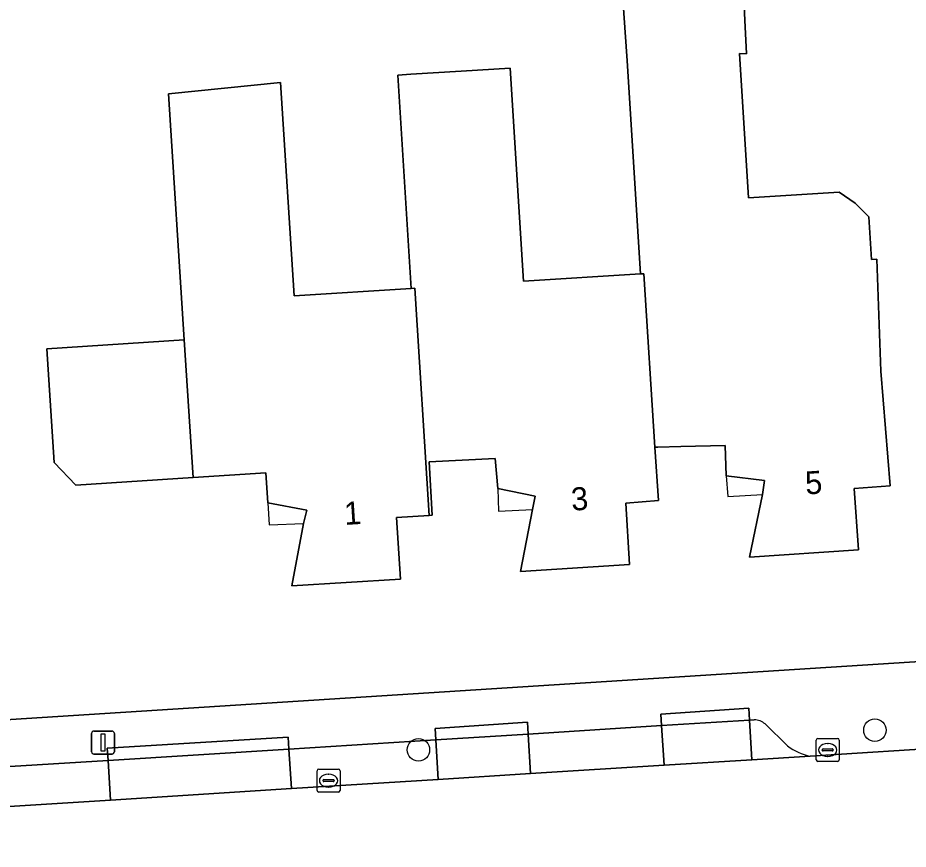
# Model space of a CAD drawing. Extents: x 159626 to 160723, y 388173 to 389416.
# Drawn here: x 160548.37 to 160587.15, y 388427.71 to 388463.92 of the extents above; entities that cross this region are included whole.
import ezdxf

# ---------------------------------------------------------------- set-up
doc = ezdxf.new("R2010")
doc.units = 0
for name, color, linetype in [('IMGEO_Boom', 7, 'Continuous'), ('IMGEO_Erf', 7, 'Continuous'), ('IMGEO_Kolk', 7, 'Continuous'), ('IMGEO_Lichtmast', 7, 'Continuous'), ('IMGEO_Pand', 7, 'Continuous'), ('IMGEO_Pand_nummerreeks', 7, 'Continuous'), ('IMGEO_Pand_overbouw', 7, 'Continuous'), ('IMGEO_Parkeervlak_open', 7, 'Continuous'), ('IMGEO_Rijbaan_lokaal_open', 7, 'Continuous'), ('IMGEO_Voetpad_open', 7, 'Continuous')]:
    doc.layers.add(name, color=color, linetype=linetype)

msp = doc.modelspace()

# ---------------------------------------------------------------- linework, layer by layer
at = {"layer": 'IMGEO_Boom'}
for centre in [(160585.699, 388432.889), (160565.815, 388432.036)]:
    msp.add_circle(centre, 0.489, dxfattribs=at)
at = {"layer": 'IMGEO_Erf'}
for points in [[(160579.903, 388466.467), (160580.102, 388462.353), (160579.794, 388462.358), (160580.19, 388456.07), (160584.142, 388456.319), (160584.842, 388455.845), (160585.435, 388455.244), (160585.551, 388453.398), (160585.781, 388453.412), (160585.963, 388448.525), (160586.361, 388443.54), (160584.797, 388443.415), (160584.985, 388440.742), (160580.238, 388440.423), (160580.798, 388443.162), (160580.883, 388443.764), (160579.227, 388443.972), (160579.173, 388445.293), (160577.242, 388445.247), (160576.242, 388445.223), (160576.12, 388445.22), (160576.268, 388442.893), (160574.857, 388442.774), (160575.008, 388440.107), (160570.266, 388439.795), (160570.787, 388442.508), (160570.899, 388443.089), (160569.275, 388443.41), (160569.151, 388444.72), (160566.289, 388444.583), (160566.417, 388442.257), (160566.286, 388442.248), (160564.857, 388442.148), (160565.035, 388439.474), (160560.297, 388439.172), (160560.808, 388441.896), (160560.958, 388442.477), (160559.253, 388442.798), (160559.165, 388444.104), (160555.998, 388443.899), (160550.897, 388443.569), (160549.944, 388444.545), (160549.624, 388449.5), (160555.616, 388449.887), (160554.932, 388460.603), (160559.813, 388461.1), (160560.398, 388451.813), (160565.501, 388452.135), (160564.916, 388461.421), (160565.482, 388461.457), (160567.677, 388461.595), (160569.809, 388461.73), (160570.394, 388452.443), (160575.486, 388452.764), (160574.901, 388462.05), (160574.621, 388466.207)], [(160521.318, 388431.7), (160527.111, 388432.027), (160588.571, 388435.938)]]:
    msp.add_lwpolyline(points, dxfattribs=at)
at = {"layer": 'IMGEO_Kolk'}
for p, q in [((160583.143, 388431.603), (160583.143, 388432.455)), ((160583.218, 388432.529), (160584.07, 388432.529)), ((160583.631, 388432.309), (160583.656, 388432.309)), ((160584.144, 388432.455), (160584.144, 388431.603)), ((160583.402, 388432.023), (160583.402, 388432.035)), ((160583.84, 388431.986), (160583.442, 388431.986)), ((160583.445, 388432.072), (160583.843, 388432.072)), ((160583.886, 388432.035), (160583.886, 388432.023)), ((160584.07, 388431.529), (160583.218, 388431.529)), ((160583.654, 388431.749), (160583.629, 388431.749)), ((160561.475, 388431.193), (160562.327, 388431.193)), ((160561.4, 388430.267), (160561.4, 388431.119)), ((160561.888, 388430.973), (160561.913, 388430.973)), ((160562.401, 388431.119), (160562.401, 388430.267)), ((160561.659, 388430.687), (160561.659, 388430.699)), ((160562.097, 388430.65), (160561.699, 388430.65)), ((160561.702, 388430.736), (160562.1, 388430.736)), ((160561.911, 388430.413), (160561.886, 388430.413)), ((160562.143, 388430.699), (160562.143, 388430.687)), ((160562.327, 388430.193), (160561.475, 388430.193))]:
    msp.add_line(p, q, dxfattribs=at)
for points in [[(160583.143, 388431.603), (160583.143, 388432.455)], [(160583.218, 388432.529), (160584.07, 388432.529)], [(160584.144, 388432.455), (160584.144, 388431.603)], [(160584.07, 388431.529), (160583.218, 388431.529)], [(160561.475, 388431.193), (160562.327, 388431.193)], [(160561.4, 388430.267), (160561.4, 388431.119)], [(160562.401, 388431.119), (160562.401, 388430.267)], [(160562.327, 388430.193), (160561.475, 388430.193)]]:
    msp.add_lwpolyline(points, dxfattribs=at)
for centre, radius, start, end in [((160583.22, 388432.453), 0.0765, 91.552, 178.448), ((160583.22, 388432.453), 0.0765, 91.552, 178.448), ((160584.068, 388432.453), 0.0765, 1.552, 88.448), ((160584.068, 388432.453), 0.0765, 1.552, 88.448), ((160583.442, 388432.032), 0.0403, 85.8775, 175.7526), ((160583.439, 388432.022), 0.0366, 178.938, 274.7102), ((160583.843, 388432.029), 0.043, 264.8664, 352.4533), ((160583.847, 388432.034), 0.0386, 1.7309, 96.639), ((160583.22, 388431.605), 0.0765, 181.552, 268.448), ((160583.22, 388431.605), 0.0765, 181.552, 268.448), ((160584.068, 388431.605), 0.0765, 271.552, 358.448), ((160584.068, 388431.605), 0.0765, 271.552, 358.448), ((160561.477, 388431.117), 0.0765, 91.552, 178.448), ((160561.477, 388431.117), 0.0765, 91.552, 178.448), ((160562.325, 388431.117), 0.0765, 1.552, 88.448), ((160562.325, 388431.117), 0.0765, 1.552, 88.448), ((160561.699, 388430.696), 0.0403, 85.8775, 175.7526), ((160561.696, 388430.686), 0.0366, 178.938, 274.7102), ((160562.1, 388430.693), 0.043, 264.8664, 352.4533), ((160562.104, 388430.698), 0.0386, 1.7309, 96.639), ((160561.477, 388430.269), 0.0765, 181.552, 268.448), ((160561.477, 388430.269), 0.0765, 181.552, 268.448), ((160562.325, 388430.269), 0.0765, 271.552, 358.448), ((160562.325, 388430.269), 0.0765, 271.552, 358.448)]:
    msp.add_arc(centre, radius, start, end, dxfattribs=at)
for centre, major_axis, ratio, start_param, end_param in [((160583.63, 388432.029), (-0.387, 0.002), 0.722429, 4.712389, 7.853982), ((160583.655, 388432.029), (-0.39, 0.002), 0.717154, 1.570796, 4.712389), ((160561.887, 388430.693), (-0.387, 0.002), 0.722429, 4.712389, 7.853982), ((160561.912, 388430.693), (-0.39, 0.002), 0.717154, 1.570796, 4.712389)]:
    msp.add_ellipse(centre, major_axis=major_axis, ratio=ratio, start_param=start_param, end_param=end_param, dxfattribs=at)
at = {"layer": 'IMGEO_Lichtmast'}
for p, q in [((160551.58, 388431.952), (160551.58, 388432.752)), ((160551.58, 388432.752), (160551.58, 388431.952)), ((160551.68, 388432.852), (160552.47, 388432.852)), ((160552.47, 388432.852), (160551.68, 388432.852)), ((160552.57, 388432.752), (160552.57, 388431.952)), ((160552.57, 388431.952), (160552.57, 388432.752)), ((160552.47, 388431.852), (160551.68, 388431.852)), ((160551.68, 388431.852), (160552.47, 388431.852))]:
    msp.add_line(p, q, dxfattribs=at)
msp.add_lwpolyline([(160552, 388432.727), (160552.15, 388432.727), (160552.15, 388431.977), (160552, 388431.977), (160552, 388432.727)], dxfattribs=at)
for centre, start, end in [((160551.68, 388432.752), 90, 180), ((160551.68, 388432.752), 90, 180), ((160552.47, 388432.752), 0, 90), ((160552.47, 388432.752), 360, 90), ((160551.68, 388431.952), 180, 270), ((160551.68, 388431.952), 180, 270), ((160552.47, 388431.952), 270, 0), ((160552.47, 388431.952), 270, 0)]:
    msp.add_arc(centre, 0.1, start, end, dxfattribs=at)
at = {"layer": 'IMGEO_Pand'}
msp.add_lwpolyline([(160574.621, 388466.207), (160574.901, 388462.05), (160575.486, 388452.764), (160575.641, 388452.774), (160576.12, 388445.22), (160576.242, 388445.223), (160577.242, 388445.247), (160579.173, 388445.293), (160579.227, 388443.972), (160580.883, 388443.764), (160580.798, 388443.162), (160580.238, 388440.423), (160584.985, 388440.742), (160584.797, 388443.415), (160586.361, 388443.54), (160585.963, 388448.525), (160585.781, 388453.412), (160585.551, 388453.398), (160585.435, 388455.244), (160584.842, 388455.845), (160584.142, 388456.319), (160580.19, 388456.07), (160579.794, 388462.358), (160580.102, 388462.353), (160579.903, 388466.467)], dxfattribs=at)
for points in [[(160575.641, 388452.774), (160575.486, 388452.764), (160570.394, 388452.443), (160569.809, 388461.73), (160567.677, 388461.595), (160565.482, 388461.457), (160564.916, 388461.421), (160565.501, 388452.135), (160565.657, 388452.145), (160566.286, 388442.248), (160566.417, 388442.257), (160566.289, 388444.583), (160569.151, 388444.72), (160569.275, 388443.41), (160570.899, 388443.089), (160570.787, 388442.508), (160570.266, 388439.795), (160575.008, 388440.107), (160574.857, 388442.774), (160576.268, 388442.893), (160576.12, 388445.22)], [(160566.286, 388442.248), (160565.657, 388452.145), (160565.501, 388452.135), (160560.398, 388451.813), (160559.813, 388461.1), (160554.932, 388460.603), (160555.616, 388449.887), (160555.998, 388443.899), (160559.165, 388444.104), (160559.253, 388442.798), (160560.958, 388442.477), (160560.808, 388441.896), (160560.297, 388439.172), (160565.035, 388439.474), (160564.857, 388442.148)], [(160555.616, 388449.887), (160549.624, 388449.5), (160549.944, 388444.545), (160550.897, 388443.569), (160555.998, 388443.899)]]:
    msp.add_lwpolyline(points, close=True, dxfattribs=at)
at = {"layer": 'IMGEO_Pand_overbouw'}
for points in [[(160580.798, 388443.162), (160580.883, 388443.764), (160579.227, 388443.972), (160579.292, 388443.075)], [(160570.787, 388442.508), (160570.899, 388443.089), (160569.275, 388443.41), (160569.303, 388442.435)], [(160559.253, 388442.798), (160559.314, 388441.832), (160560.808, 388441.896), (160560.958, 388442.477)]]:
    msp.add_lwpolyline(points, close=True, dxfattribs=at)
at = {"layer": 'IMGEO_Parkeervlak_open'}
for points in [[(160576.407, 388433.089), (160570.6, 388432.723), (160570.704, 388430.997), (160576.515, 388431.361)], [(160580.233, 388433.33), (160576.407, 388433.089), (160576.515, 388431.361), (160580.341, 388431.601)], [(160570.6, 388432.723), (160566.573, 388432.469), (160566.68, 388430.744), (160570.704, 388430.997)], [(160566.573, 388432.469), (160560.171, 388432.066), (160560.282, 388430.343), (160566.68, 388430.744)], [(160560.171, 388432.066), (160552.294, 388431.569), (160552.399, 388429.848), (160560.282, 388430.343)]]:
    msp.add_lwpolyline(points, close=True, dxfattribs=at)
for points in [[(160580.442, 388433.343), (160580.233, 388433.33), (160580.341, 388431.601), (160582.875, 388431.76)], [(160581.89, 388432.203), (160580.915, 388433.16)], [(160525.71, 388428.174), (160552.399, 388429.848), (160552.294, 388431.569)], [(160552.294, 388431.569), (160528.011, 388430.089)]]:
    msp.add_lwpolyline(points, dxfattribs=at)
for centre, radius, start, end in [((160580.455, 388432.673), 0.67, 46.6081, 91.0898), ((160583.437, 388434.325), 2.626, 233.9167, 257.652)]:
    msp.add_arc(centre, radius, start, end, dxfattribs=at)
at = {"layer": 'IMGEO_Rijbaan_lokaal_open'}
msp.add_lwpolyline([(160589.246, 388432.16), (160582.875, 388431.76), (160580.341, 388431.601), (160576.515, 388431.361), (160570.704, 388430.997), (160566.68, 388430.744), (160560.282, 388430.343), (160552.399, 388429.848), (160525.71, 388428.174), (160525.02, 388428.13), (160525.26, 388423.086), (160542.187, 388424.165), (160545.973, 388424.406), (160553.441, 388424.882), (160557.225, 388425.123), (160564.339, 388425.575), (160568.126, 388425.816), (160575.667, 388426.296), (160579.442, 388426.54), (160583.939, 388426.83), (160587.17, 388427.056), (160590.95, 388427.367)], dxfattribs=at)
at = {"layer": 'IMGEO_Voetpad_open'}
for points in [[(160588.571, 388435.938), (160527.111, 388432.027), (160521.318, 388431.7)], [(160528.011, 388430.089), (160552.294, 388431.569), (160552.261, 388432.105), (160560.139, 388432.584), (160560.171, 388432.066), (160566.573, 388432.469), (160566.542, 388432.964), (160570.561, 388433.241), (160570.6, 388432.723), (160576.407, 388433.089), (160576.376, 388433.587), (160580.201, 388433.845), (160580.233, 388433.33), (160580.442, 388433.343)], [(160580.915, 388433.16), (160581.89, 388432.203)], [(160582.875, 388431.76), (160589.246, 388432.16)]]:
    msp.add_lwpolyline(points, dxfattribs=at)
for points in [[(160580.201, 388433.845), (160576.376, 388433.587), (160576.407, 388433.089), (160580.233, 388433.33)], [(160570.561, 388433.241), (160566.542, 388432.964), (160566.573, 388432.469), (160570.6, 388432.723)], [(160560.139, 388432.584), (160552.261, 388432.105), (160552.294, 388431.569), (160560.171, 388432.066)]]:
    msp.add_lwpolyline(points, close=True, dxfattribs=at)
for centre, radius, start, end in [((160580.455, 388432.673), 0.67, 46.6081, 91.0898), ((160583.437, 388434.325), 2.626, 233.9167, 257.652)]:
    msp.add_arc(centre, radius, start, end, dxfattribs=at)

# ---------------------------------------------------------------- texts
at = {"layer": 'IMGEO_Pand_nummerreeks'}
for s, rotation, p in [('5', 3.8445, (160582.692, 388443.153)), ('3', 3.7643, (160572.497, 388442.448)), ('1', 3.6471, (160562.608, 388441.827))]:
    msp.add_text(s, height=1, rotation=rotation, dxfattribs=at).set_placement(p)

doc.saveas('drawing.dxf')
